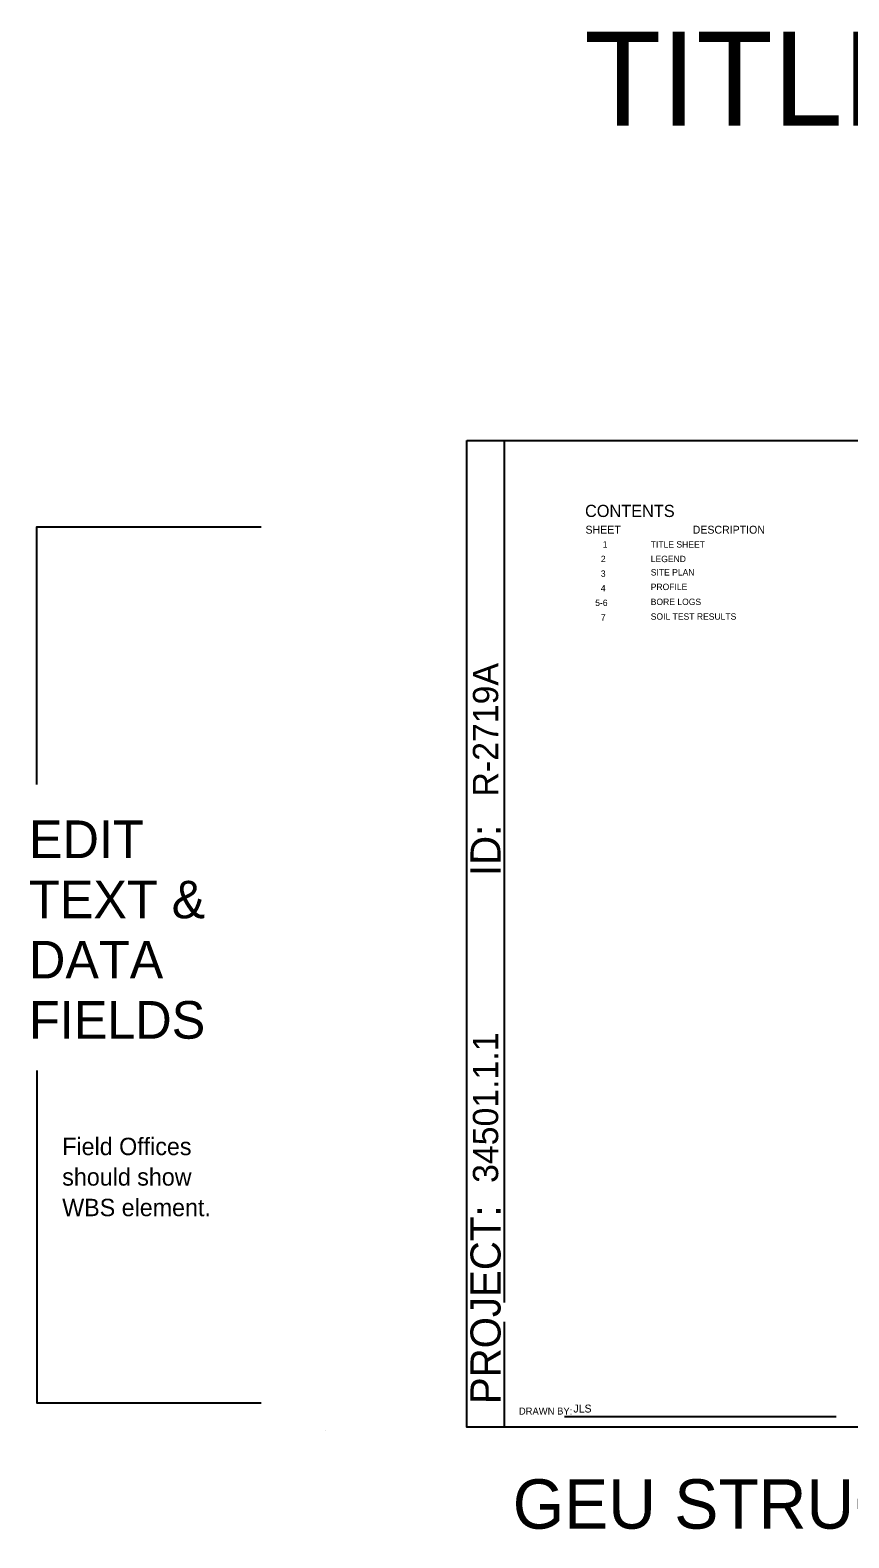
# Model space of a CAD drawing. Extents: x 278710 to 279187, y 171464 to 171625.
# Drawn here: x 278709.7 to 278796.7, y 171464.3 to 171624.6 of the extents above; entities that cross this region are included whole.
import ezdxf

# ---------------------------------------------------------------- set-up
doc = ezdxf.new("R2010")
doc.units = 0
doc.layers.add('Geotech Sheets and Borders Cell', color=7, linetype='Continuous')
doc.layers.add('Prop Strc Sect_ Misc - User Comment (Tx - small)', color=7, linetype='Continuous')

msp = doc.modelspace()

# ---------------------------------------------------------------- linework, layer by layer
at = {"layer": 'Geotech Sheets and Borders Cell'}
for p, q in [((278760.06, 171580.95), (278760.06, 171489.33)), ((278760.06, 171487.27), (278760.06, 171476.08)), ((278766.45, 171477.22), (278795.32, 171477.22)), ((278741.09, 171475.75), (278741.09, 171475.75))]:
    msp.add_line(p, q, dxfattribs=at)
msp.add_lwpolyline([(278756.09, 171580.95), (278907.34, 171580.95), (278907.34, 171476.08), (278756.09, 171476.08)], close=True, dxfattribs=at)
for points in [[(278710.39, 171544.39), (278710.39, 171571.77), (278734.25, 171571.77)], [(278710.39, 171513.98), (278710.39, 171478.65), (278734.25, 171478.65)]]:
    msp.add_lwpolyline(points, dxfattribs=at)

# ---------------------------------------------------------------- texts
for s, height, rotation, p in [('CONTENTS', 1.295, 359.9916, (278768.65, 171572.83)), ('R-2719A', 2.688, 90, (278759.42, 171543.12)), ('ID:', 3.195, 89.9873, (278759.67, 171534.66)), ('34501.1.1', 2.688, 90, (278759.42, 171502.04)), ('PROJECT:', 3.195, 89.9873, (278759.67, 171478.52)), ('DRAWN BY:', 0.749, 0.1322, (278761.62, 171477.4))]:
    msp.add_text(s, height=height, rotation=rotation, dxfattribs=at).set_placement(p)
for s, height, p in [('SHEET', 0.84, (278768.7, 171571.06)), ('DESCRIPTION', 0.84, (278780.09, 171571.06)), ('1', 0.68, (278770.53, 171569.58)), ('TITLE SHEET', 0.68, (278775.63, 171569.58)), ('2', 0.68, (278770.33, 171568.03)), ('LEGEND', 0.68, (278775.63, 171568.03)), ('3', 0.68, (278770.33, 171566.47)), ('SITE PLAN', 0.68, (278775.63, 171566.61)), ('4', 0.68, (278770.33, 171564.92)), ('PROFILE', 0.68, (278775.63, 171565.06)), ('5-6', 0.68, (278769.73, 171563.37)), ('BORE LOGS ', 0.68, (278775.63, 171563.47)), ('7', 0.68, (278770.33, 171561.81)), ('SOIL TEST RESULTS', 0.68, (278775.63, 171561.91)), ('EDIT', 4, (278709.57, 171536.57)), ('TEXT &', 4, (278709.57, 171530.17)), ('DATA', 4, (278709.57, 171523.77)), ('FIELDS', 4, (278709.57, 171517.37)), ('Field Offices', 1.848, (278713.1, 171504.99)), ('should show', 1.848, (278713.1, 171501.75)), ('WBS element.', 1.848, (278713.1, 171498.5)), ('JLS', 0.84, (278767.41, 171477.63)), ('GEU STRUCTURE TITLE SHEET, ENGLISH', 5.25, (278760.97, 171465.28))]:
    msp.add_text(s, height=height, dxfattribs=at).set_placement(p)
at = {"layer": 'Prop Strc Sect_ Misc - User Comment (Tx - small)'}
msp.add_text('TITLE SHEET: 11" x 17"', height=10, dxfattribs=at).set_placement((278768.57, 171614.44))

doc.saveas('drawing.dxf')
